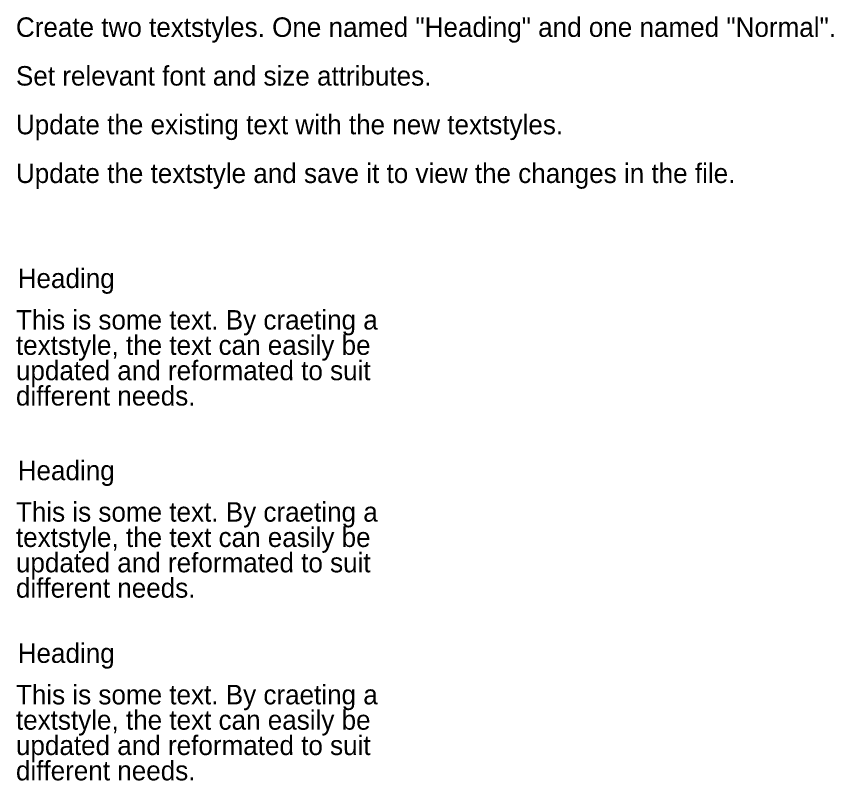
# Model space of a CAD drawing. Extents: x 1517703.3 to 1517715.9, y 6495363.4 to 6495375.2.
import ezdxf

# ---------------------------------------------------------------- set-up
doc = ezdxf.new("R2010")
doc.units = 0
doc.layers.add('Instruktioner', color=7, linetype='Continuous')
doc.layers.add('Lager 1', color=7, linetype='Continuous')

msp = doc.modelspace()

# ---------------------------------------------------------------- texts
at = {"layer": 'Instruktioner'}
for s, p in [('Create two textstyles. One named "Heading" and one named "Normal".', (1517703.318, 6495374.88)), ('Set relevant font and size attributes.', (1517703.318, 6495374.13)), ('Update the existing text with the new textstyles.', (1517703.318, 6495373.38)), ('Update the textstyle and save it to view the changes in the file.', (1517703.318, 6495372.63))]:
    msp.add_text(s, height=0.3, dxfattribs=at).set_placement(p)
at = {"layer": 'Lager 1'}
for s, p in [('Heading', (1517703.345, 6495371.013)), ('This is some text. By craeting a ', (1517703.318, 6495370.374)), ('textstyle, the text can easily be ', (1517703.318, 6495369.984)), ('updated and reformated to suit', (1517703.318, 6495369.594)), ('different needs.', (1517703.318, 6495369.204)), ('Heading', (1517703.345, 6495368.055)), ('This is some text. By craeting a ', (1517703.318, 6495367.416)), ('textstyle, the text can easily be ', (1517703.318, 6495367.026)), ('updated and reformated to suit', (1517703.318, 6495366.636)), ('different needs.', (1517703.318, 6495366.246)), ('Heading', (1517703.345, 6495365.242)), ('This is some text. By craeting a ', (1517703.318, 6495364.603)), ('textstyle, the text can easily be ', (1517703.318, 6495364.213)), ('updated and reformated to suit', (1517703.318, 6495363.823)), ('different needs.', (1517703.318, 6495363.433))]:
    msp.add_text(s, height=0.3, dxfattribs=at).set_placement(p)

doc.saveas('drawing.dxf')
